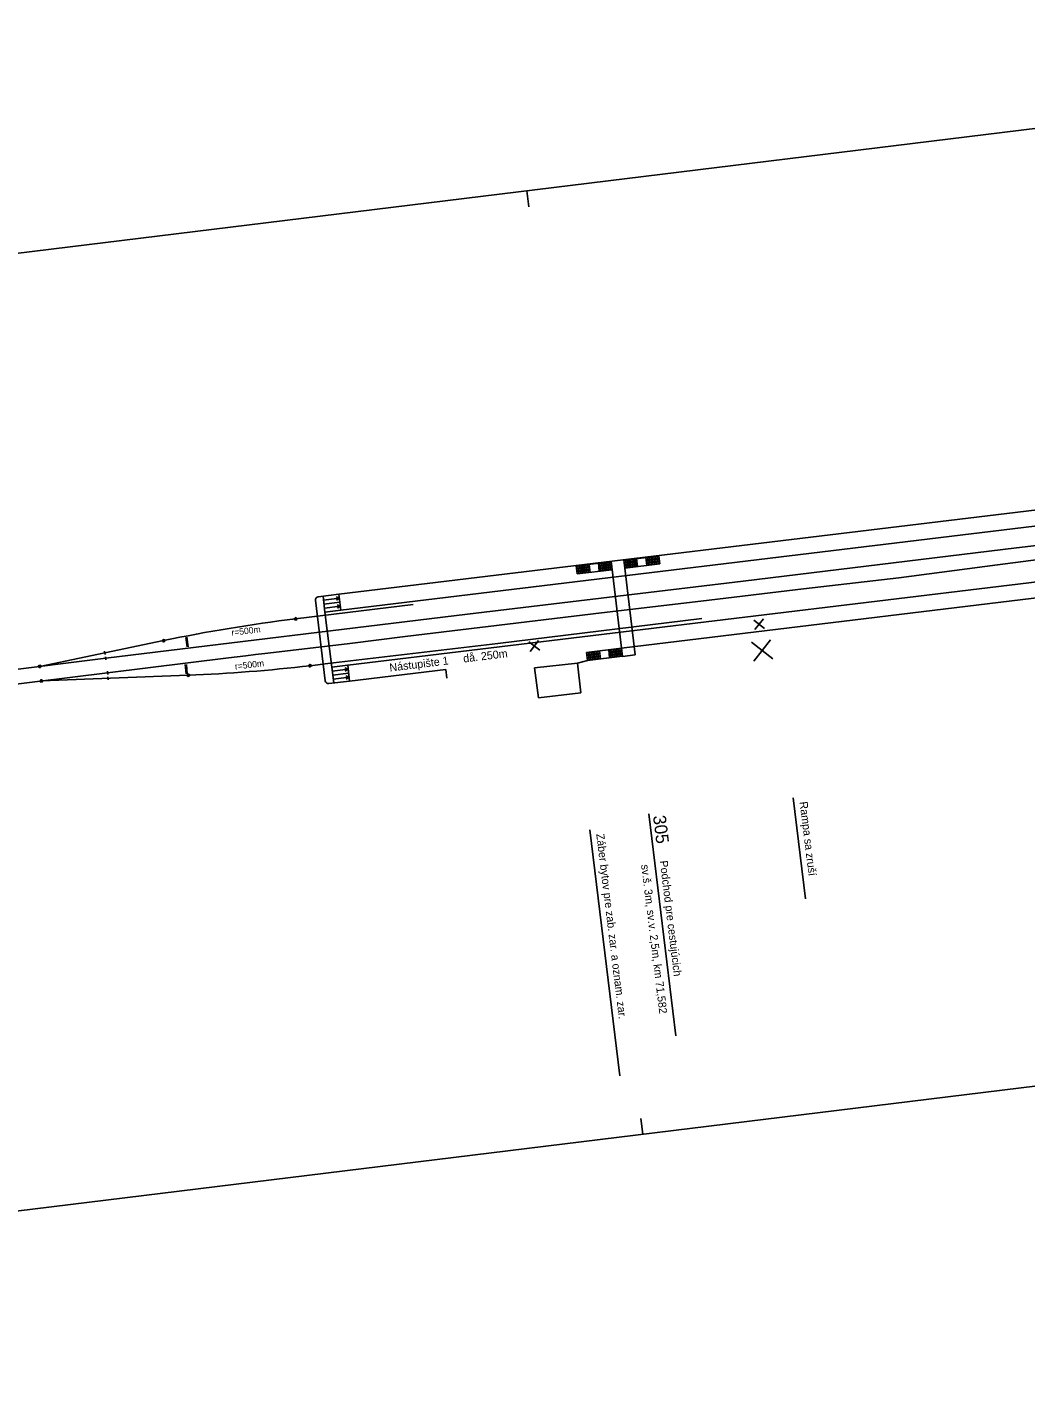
# Model space of a CAD drawing. Extents: x -559083 to -556962, y -1276579 to -1276028.
# Drawn here: x -558613.7 to -558301.5, y -1276578.6 to -1276155.9 of the extents above; entities that cross this region are included whole.
import ezdxf

# ---------------------------------------------------------------- set-up
doc = ezdxf.new("R2010")
doc.units = 0
for name, color, linetype in [('kolaj s', 7, 'Continuous'), ('popis 25', 7, 'Continuous'), ('popis 50', 7, 'Continuous'), ('ram vykresu', 7, 'Continuous'), ('stavby', 7, 'Continuous')]:
    doc.layers.add(name, color=color, linetype=linetype)

msp = doc.modelspace()

# ---------------------------------------------------------------- linework, layer by layer
at = {"layer": 'kolaj s'}
for p, q in [((-558216.7, -1276308.45), (-558304.47, -1276318.63)), ((-558304.47, -1276318.63), (-558389.85, -1276329)), ((-558310.43, -1276323.91), (-558281.77, -1276320.27)), ((-558341.2, -1276327.94), (-558310.43, -1276323.91)), ((-558389.85, -1276329), (-558476.02, -1276339.38)), ((-558371.02, -1276331.43), (-558341.2, -1276327.94)), ((-558403.12, -1276335.24), (-558371.02, -1276331.43)), ((-558529.79, -1276340.8), (-558493.06, -1276336.31)), ((-558434.14, -1276338.91), (-558403.12, -1276335.24)), ((-558476.02, -1276339.38), (-558589.1, -1276353.13)), ((-558529.79, -1276340.8), (-558529.79, -1276340.8)), ((-558495.53, -1276346.37), (-558463.56, -1276342.5)), ((-558466.61, -1276348.48), (-558402.76, -1276340.67)), ((-558463.56, -1276342.5), (-558434.14, -1276338.91)), ((-558512.84, -1276348.47), (-558495.53, -1276346.37)), ((-558609.74, -1276355.66), (-558571.03, -1276347.6)), ((-558589.48, -1276350.93), (-558589.28, -1276351.91)), ((-558571.03, -1276347.6), (-558571.03, -1276347.6)), ((-558571.03, -1276347.6), (-558571.03, -1276347.6)), ((-558539.35, -1276351.63), (-558533.11, -1276350.87)), ((-558533.11, -1276350.87), (-558512.84, -1276348.47)), ((-558466.61, -1276348.48), (-558519.67, -1276354.8)), ((-558630.38, -1276358.2), (-558589.1, -1276353.13)), ((-558589.38, -1276351.42), (-558589.38, -1276351.42)), ((-558589.16, -1276352.63), (-558589.04, -1276353.62)), ((-558589.1, -1276353.13), (-558589.1, -1276353.13)), ((-558588.54, -1276357.65), (-558550.77, -1276353.01)), ((-558550.77, -1276353.01), (-558548.02, -1276352.68)), ((-558548.02, -1276352.68), (-558545.36, -1276352.35)), ((-558545.36, -1276352.35), (-558542.33, -1276351.99)), ((-558542.33, -1276351.99), (-558539.35, -1276351.63)), ((-558519.67, -1276354.8), (-558525.25, -1276355.45)), ((-558629.83, -1276362.72), (-558588.54, -1276357.65)), ((-558609.74, -1276355.66), (-558609.74, -1276355.66)), ((-558609.19, -1276360.19), (-558563.31, -1276358.4)), ((-558588.6, -1276357.16), (-558588.48, -1276358.15)), ((-558588.54, -1276357.65), (-558588.54, -1276357.65)), ((-558588.43, -1276358.87), (-558588.39, -1276359.87)), ((-558588.41, -1276359.37), (-558588.41, -1276359.37)), ((-558563.31, -1276358.4), (-558563.31, -1276358.4)), ((-558563.31, -1276358.4), (-558563.31, -1276358.4)), ((-558525.25, -1276355.45), (-558525.25, -1276355.45)), ((-558609.19, -1276360.19), (-558609.19, -1276360.19))]:
    msp.add_line(p, q, dxfattribs=at)
for points in [[(-558529.74, -1276341.2), (-558530.11, -1276341.04), (-558530.16, -1276340.65), (-558529.84, -1276340.4), (-558529.47, -1276340.56), (-558529.42, -1276340.96), (-558529.74, -1276341.2)], [(-558570.95, -1276347.99), (-558571.32, -1276347.87), (-558571.41, -1276347.48), (-558571.11, -1276347.21), (-558570.73, -1276347.34), (-558570.65, -1276347.73), (-558570.95, -1276347.99)], [(-558571.11, -1276347.21), (-558570.73, -1276347.33), (-558570.65, -1276347.72), (-558570.95, -1276347.99), (-558571.33, -1276347.86), (-558571.41, -1276347.48), (-558571.11, -1276347.21)], [(-558609.34, -1276355.61), (-558609.5, -1276355.98), (-558609.9, -1276356.03), (-558610.14, -1276355.71), (-558609.98, -1276355.34), (-558609.59, -1276355.29), (-558609.34, -1276355.61)], [(-558525.2, -1276355.85), (-558525.57, -1276355.69), (-558525.62, -1276355.29), (-558525.3, -1276355.05), (-558524.93, -1276355.21), (-558524.88, -1276355.61), (-558525.2, -1276355.85)], [(-558563.33, -1276358), (-558562.98, -1276358.18), (-558562.96, -1276358.58), (-558563.3, -1276358.79), (-558563.65, -1276358.61), (-558563.67, -1276358.21), (-558563.33, -1276358)], [(-558563.33, -1276358), (-558562.98, -1276358.18), (-558562.96, -1276358.58), (-558563.3, -1276358.79), (-558563.65, -1276358.61), (-558563.67, -1276358.21), (-558563.33, -1276358)], [(-558608.79, -1276360.14), (-558608.95, -1276360.5), (-558609.34, -1276360.55), (-558609.58, -1276360.23), (-558609.43, -1276359.86), (-558609.03, -1276359.82), (-558608.79, -1276360.14)]]:
    msp.add_lwpolyline(points, dxfattribs=at)
for centre, start, end in [((-558469.13, -1276837.11), 96.9682, 101.759), ((-558582.82, -1275858.78), 272.2354, 276.6111)]:
    msp.add_arc(centre, 500, start, end, dxfattribs=at)
at = {"layer": 'popis 25'}
for p, q in [((-558564.04, -1276346.61), (-558563.61, -1276349.57)), ((-558563.73, -1276346.56), (-558563.29, -1276349.52)), ((-558564.23, -1276355.06), (-558563.95, -1276358.03)), ((-558563.91, -1276355.03), (-558563.63, -1276358.01))]:
    msp.add_line(p, q, dxfattribs=at)
at = {"layer": 'popis 50'}
for p, q in [((-558427.59, -1276352.52), (-558431.19, -1276322.8)), ((-558423.62, -1276352.04), (-558427.21, -1276322.32)), ((-558383.19, -1276343.81), (-558386.55, -1276341.18)), ((-558383.55, -1276340.81), (-558386.19, -1276344.18)), ((-558453.48, -1276350.62), (-558456.85, -1276347.99)), ((-558453.85, -1276347.62), (-558456.49, -1276350.99)), ((-558380.57, -1276353.32), (-558387.31, -1276348.06)), ((-558381.31, -1276347.32), (-558386.57, -1276354.06)), ((-558438.54, -1276353.86), (-558441.62, -1276354.61)), ((-558427.62, -1276352.52), (-558423.62, -1276352.04)), ((-558482.52, -1276359.32), (-558482.85, -1276356.6)), ((-558374.3, -1276396.68), (-558370.42, -1276428.31)), ((-558419.4, -1276401.76), (-558410.89, -1276471.1)), ((-558437.84, -1276406.72), (-558428.41, -1276483.56))]:
    msp.add_line(p, q, dxfattribs=at)
at = {"layer": 'ram vykresu'}
for p, q in [((-559082.77, -1276283.84), (-558040.59, -1276155.88)), ((-558456.85, -1276212.03), (-558457.46, -1276207.06)), ((-558004.4, -1276450.67), (-559046.57, -1276578.63)), ((-558421.27, -1276501.85), (-558421.88, -1276496.89))]:
    msp.add_line(p, q, dxfattribs=at)
at = {"layer": 'stavby'}
for p, q in [((-558516.24, -1276333.09), (-558268.05, -1276303.06)), ((-558267.45, -1276308.02), (-558515.64, -1276338.06)), ((-558427.15, -1276322.47), (-558416.23, -1276321.17)), ((-558418.78, -1276321.47), (-558418.48, -1276323.96)), ((-558418.28, -1276321.41), (-558417.99, -1276323.9)), ((-558417.79, -1276321.35), (-558417.49, -1276323.84)), ((-558417.29, -1276321.3), (-558416.99, -1276323.78)), ((-558416.8, -1276321.24), (-558416.5, -1276323.72)), ((-558416.23, -1276321.17), (-558415.93, -1276323.65)), ((-558442.09, -1276324.28), (-558431.17, -1276322.98)), ((-558441.8, -1276326.76), (-558442.09, -1276324.28)), ((-558430.87, -1276325.46), (-558441.8, -1276326.76)), ((-558441.23, -1276326.69), (-558441.52, -1276324.21)), ((-558440.73, -1276326.63), (-558441.03, -1276324.15)), ((-558440.23, -1276326.57), (-558440.53, -1276324.09)), ((-558439.74, -1276326.51), (-558440.04, -1276324.03)), ((-558439.24, -1276326.45), (-558439.54, -1276323.97)), ((-558438.75, -1276326.4), (-558439.04, -1276323.91)), ((-558438.25, -1276326.34), (-558438.55, -1276323.85)), ((-558437.75, -1276326.28), (-558438.05, -1276323.79)), ((-558435.14, -1276323.45), (-558434.84, -1276325.93)), ((-558434.64, -1276323.39), (-558434.35, -1276325.88)), ((-558434.15, -1276323.33), (-558433.85, -1276325.82)), ((-558433.65, -1276323.27), (-558433.35, -1276325.76)), ((-558433.16, -1276323.22), (-558432.86, -1276325.7)), ((-558432.66, -1276323.16), (-558432.36, -1276325.64)), ((-558432.16, -1276323.1), (-558431.87, -1276325.58)), ((-558431.67, -1276323.04), (-558431.37, -1276325.52)), ((-558431.17, -1276322.98), (-558430.87, -1276325.46)), ((-558426.85, -1276324.95), (-558427.15, -1276322.47)), ((-558415.93, -1276323.65), (-558426.85, -1276324.95)), ((-558426.36, -1276324.89), (-558426.65, -1276322.41)), ((-558425.86, -1276324.83), (-558426.16, -1276322.35)), ((-558425.36, -1276324.77), (-558425.66, -1276322.29)), ((-558424.87, -1276324.71), (-558425.16, -1276322.23)), ((-558424.37, -1276324.65), (-558424.67, -1276322.17)), ((-558423.88, -1276324.59), (-558424.17, -1276322.11)), ((-558423.38, -1276324.54), (-558423.68, -1276322.05)), ((-558422.88, -1276324.48), (-558423.18, -1276321.99)), ((-558420.27, -1276321.65), (-558419.97, -1276324.13)), ((-558419.77, -1276321.59), (-558419.48, -1276324.07)), ((-558419.28, -1276321.53), (-558418.98, -1276324.02)), ((-558522.69, -1276333.88), (-558516.24, -1276333.09)), ((-558520.6, -1276338.67), (-558521.2, -1276333.7)), ((-558517.11, -1276333.95), (-558516.09, -1276334.33)), ((-558516.24, -1276333.09), (-558515.63, -1276338.05)), ((-558520.52, -1276360.16), (-558523.56, -1276335)), ((-558516.09, -1276334.33), (-558521.05, -1276334.94)), ((-558515.94, -1276335.57), (-558520.9, -1276336.18)), ((-558515.79, -1276336.81), (-558520.75, -1276337.42)), ((-558515.63, -1276338.05), (-558520.6, -1276338.67)), ((-558516.98, -1276334.95), (-558516.09, -1276334.33)), ((-558516.8, -1276336.43), (-558515.79, -1276336.81)), ((-558516.68, -1276337.43), (-558515.79, -1276336.81)), ((-558520.6, -1276338.67), (-558518.45, -1276355.88)), ((-558438.86, -1276351.31), (-558427.93, -1276350.01)), ((-558436.5, -1276353.55), (-558436.8, -1276351.06)), ((-558436.01, -1276353.49), (-558436.3, -1276351.01)), ((-558435.51, -1276353.43), (-558435.81, -1276350.95)), ((-558435.01, -1276353.37), (-558435.31, -1276350.89)), ((-558434.52, -1276353.31), (-558434.81, -1276350.83)), ((-558431.91, -1276350.49), (-558431.61, -1276352.97)), ((-558431.41, -1276350.43), (-558431.11, -1276352.91)), ((-558430.91, -1276350.37), (-558430.62, -1276352.85)), ((-558430.42, -1276350.31), (-558430.12, -1276352.79)), ((-558429.92, -1276350.25), (-558429.62, -1276352.73)), ((-558429.42, -1276350.19), (-558429.13, -1276352.67)), ((-558428.93, -1276350.13), (-558428.63, -1276352.61)), ((-558428.43, -1276350.07), (-558428.13, -1276352.55)), ((-558427.93, -1276350.01), (-558427.64, -1276352.49)), ((-558518.45, -1276355.88), (-558513.49, -1276355.27)), ((-558513.49, -1276355.27), (-558512.88, -1276360.23)), ((-558455.1, -1276356.11), (-558441.62, -1276354.61)), ((-558441.62, -1276354.61), (-558440.57, -1276363.88)), ((-558438.56, -1276353.8), (-558438.86, -1276351.31)), ((-558427.64, -1276352.49), (-558438.56, -1276353.8)), ((-558437.99, -1276353.72), (-558438.29, -1276351.24)), ((-558437.5, -1276353.67), (-558437.79, -1276351.18)), ((-558437, -1276353.61), (-558437.3, -1276351.12)), ((-558427.62, -1276352.52), (-558427.62, -1276352.52)), ((-558517.84, -1276360.84), (-558518.45, -1276355.88)), ((-558513.34, -1276356.51), (-558518.3, -1276357.12)), ((-558513.19, -1276357.75), (-558518.15, -1276358.36)), ((-558513.03, -1276358.99), (-558518, -1276359.6)), ((-558514.35, -1276356.13), (-558513.34, -1276356.51)), ((-558514.23, -1276357.13), (-558513.34, -1276356.51)), ((-558514.05, -1276358.61), (-558513.03, -1276358.99)), ((-558513.93, -1276359.61), (-558513.03, -1276358.99)), ((-558453.9, -1276365.47), (-558455.1, -1276356.11)), ((-558512.88, -1276360.23), (-558519.4, -1276361.04)), ((-558440.57, -1276363.88), (-558453.9, -1276365.47))]:
    msp.add_line(p, q, dxfattribs=at)
msp.add_lwpolyline([(-558482.85, -1276356.6), (-558512.89, -1276360.24), (-558513.49, -1276355.27), (-558265.3, -1276325.24), (-558264.7, -1276330.2), (-558427.9, -1276349.95)], dxfattribs=at)
for centre, start, end in [((-558522.57, -1276334.88), 97.0504, 186.9061), ((-558519.52, -1276360.04), 186.9117, 276.9742)]:
    msp.add_arc(centre, 1, start, end, dxfattribs=at)

# ---------------------------------------------------------------- texts
at = {"layer": 'popis 25'}
for p in [(-558549.69, -1276346.1), (-558548.61, -1276356.68)]:
    msp.add_text('r=500m', height=2, rotation=6.8, dxfattribs=at).set_placement(p)
at = {"layer": 'popis 50'}
for s, rotation, p in [('Nástupište 1     då. 250m', 7, (-558500.28, -1276357.29)), ('Rampa sa zruší', 277, (-558372.26, -1276398.03)), ('Záber bytov pre zab. zar. a oznam. zar.', 277, (-558435.81, -1276408.07)), ('sv.š. 3m, sv.v. 2,5m, km 71,582', 277, (-558421.79, -1276417.67)), ('Podchod pre cestujúcich', 277, (-558415.97, -1276416.47))]:
    msp.add_text(s, height=2.5, rotation=rotation, dxfattribs=at).set_placement(p)
at = {"layer": 'stavby'}
msp.add_text('305', height=4, rotation=277.0019, dxfattribs=at).set_placement((-558418.07, -1276402.41))

doc.saveas('drawing.dxf')
